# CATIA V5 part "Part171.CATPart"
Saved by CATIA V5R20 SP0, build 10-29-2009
Part number: FA 126700-2 comprimido
Revision: ANY
Definition: UNKNOWN
Nomenclature: FA 126700-2 comprimido
Source: Unknown
Bounding box of the stored display mesh (mm): x -2.8 to 2.8, y 0 to 5, z -2.8 to 2.8
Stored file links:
  C:\Users\Utente\Desktop\IO LAVORO\3D X SITO CF\CUMSA\3D files FA\FA 126708-20\Part171.CATPart
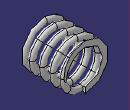
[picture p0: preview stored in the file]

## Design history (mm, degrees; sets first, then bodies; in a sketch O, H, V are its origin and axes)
Body1 "Cortar-Extruir1" (main body)
  Solid1: solid without history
